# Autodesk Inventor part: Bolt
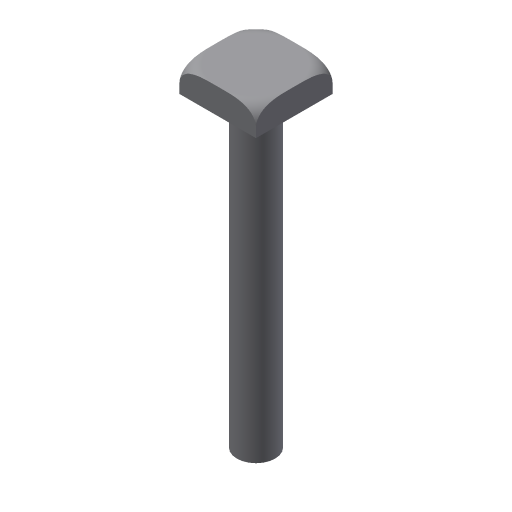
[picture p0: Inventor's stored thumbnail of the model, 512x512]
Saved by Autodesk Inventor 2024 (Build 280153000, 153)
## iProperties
Created: 2009-04
Part Number: Bolt
Document SubType Name: Modeling
Designer: Sham
Density: 1 g/cm^3
Material: Generic
Appearance: Default
Author: Sham
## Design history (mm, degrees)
sketch "Sketch1"
  geometry: L1 (-12, 12)-(12, 12); L2 (12, 12)-(12, -12); L3 (12, -12)-(-12, -12); L4 (-12, -12)-(-12, 12); 1 further point
  constraints: 8 end point, 2 parallel, 2 perpendicular, 1 horizontal, 1 other
  dimensions: "d0" = 24 distance of L1.start L1.end; "d1" = 12 distance from line of L2 point (0, 0); "d2" = 12 distance from line of L1 point (0, 0)
extrude "Extrusion1" new body sketch "Sketch1" distance "d3" = 8; taper "d4" = 0 deg
sketch "Sketch2"
  geometry: C1 r 6 at (0, 0)
  constraints: 1 centre point
  dimensions: "d5" = 12 diameter of C1
extrude "Extrusion2" join sketch "Sketch2" distance "d6" = 96; taper "d7" = 0 deg
workpoint "Work Point1"
workplane "Work Plane1"
sketch "Sketch3"
  geometry: L1 (33.941, 5)-(33.941, 6); L2 (28.941, 0)-(28.405, 0); L3 (16.971, 125.007)-(16.971, -22.043) reference; A1 r 5 centre (28.941, 5) between (28.941, 0) and (33.941, 5); 1 further point
  constraints: 4 end point, 2 point on circle, 2 point on line, 2 tangent, 1 centre point, 1 perpendicular
  dimensions: "d10" = 5 radius of A1
revolve "Revolution1" sketch "Sketch3" stored, may be unused: angle "d12" = 90 deg
body "Solid1"
other parameters: "d11" = 90 deg
